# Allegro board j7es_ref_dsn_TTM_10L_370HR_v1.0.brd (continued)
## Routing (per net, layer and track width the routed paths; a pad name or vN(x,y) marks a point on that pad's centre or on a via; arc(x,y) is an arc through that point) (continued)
SOC_SERDES2_REFCLK_P: length 43.3
  TOP w0.122: U9.AD12 101.05,78.95 v1(101.45,79.35)
  L4-SIGNAL w0.099: TPX426.1 99.16,120.77 arc(99.26,120.75) 99.33,120.7 99.34,120.69 arc(99.38,120.64) 99.39,120.58 99.39,120.57 arc(99.39,120.55) 99.39,120.53 99.39,119.58 arc(99.31,119.18) 99.08,118.84 arc(98.92,118.59) 98.86,118.29 98.86,102.57 arc(98.96,102.06) 99.24,101.63 99.78,101.1 arc(100.26,100.38) 100.43,99.52 100.43,89.51 arc(100.56,88.87) 100.92,88.32 100.94,88.3 arc(101.13,88.02) 101.19,87.7 101.19,83.94 101.07,83.48 101.07,80.09 arc(101.07,80.04) 101.07,79.99 arc(101.15,79.72) 101.31,79.49 v1(101.45,79.35)
SOC_SERDES4_REFCLK_N: length 50.2
  TOP w0.119: U9.E7 v1(105.45,63.35)
  L9-SIGNAL w0.076: TPX396.1 132.94,27.07 132.94,30.91 131.02,32.83 128.99,32.83 114.51,47.31 114.51,47.31 106.25,55.56 106.25,59.55 106.61,59.91 106.61,61.09 106.4,61.3 106.19,61.3 105.81,61.69 105.81,62.69 105.45,63.05 v1(105.45,63.35)
SOC_SERDES4_REFCLK_P: length 50.4
  TOP w0.119: U9.E8 v1(104.65,63.35)
  L9-SIGNAL w0.076: v1(104.65,63.35) 105.1,62.9 105.1,62.4 105.31,62.19 105.31,62.1 105.1,61.89 105.1,61.6 105.31,61.39 105.51,61.39 105.81,61.09 105.81,59.79 106.04,59.55 106.04,55.48 114.42,47.1 114.43,47.1 128.9,32.63 130.94,32.63 132.74,30.83 132.74,27.07 TPX397.1
SOC_TCK: length 31.8
  TOP w0.229: v1(87.05,63.35) 87.45,63.75 U9.E29 ; J1011.3 v1(53.85,55.6)
  L4-SIGNAL w0.097: v1(87.05,63.35) 60.43,63.35 v1(58.8,61.71)
  BOTTOM w0.229: 53.09,55.62 53.1,55.6 v1(53.85,55.6)
SOC_TDI: length 77.9
  TOP w0.191: U9.V1 110.25,74.54 v1(110.25,74.55)
  TOP w0.229: U131.4 v1(58.15,50.27)
  BOTTOM w0.127: v1(58.15,50.27) 59.18,51.3 59.18,52.82 60.58,54.22 72.26,54.22 76.96,58.92 96.14,58.92 96.52,58.54 112.01,58.54 112.78,59.3 112.78,73.14 111.37,74.55 v1(110.25,74.55)
SOC_TDO: length 75.3
  TOP w0.191: v1(108.65,74.55) 108.65,74.54 U9.V3
  TOP w0.229: U130.2 v1(58.17,56)
  BOTTOM w0.127: v1(58.17,56) 59.18,54.98 71.95,54.98 76.65,59.68 96.45,59.68 96.84,59.3 111.7,59.3 112.01,59.61 112.01,72.49 111.4,73.11 109.54,73.11 109.06,73.59 109.06,74.14 v1(108.65,74.55)
SOC_TMS: length 76.5
  TOP w0.191: v1(109.45,74.55) 109.05,74.15 U9.V2
  TOP w0.229: U129.4 v1(58.15,52.81)
  BOTTOM w0.127: v1(58.15,52.81) 59.94,54.6 72.11,54.6 76.8,59.3 96.3,59.3 96.68,58.92 111.86,58.92 112.39,59.46 112.39,72.89 111.12,74.16 109.85,74.16 v1(109.45,74.55)
  BOTTOM w0.229: R1219.2 v1(44.96,55.36)
SOC_TRST#: length 50.2
  TOP w0.229: U9.F24 91.05,64.15 v1(91.05,64.15)
  L7-SIGNAL w0.097: v1(60.2,57.27) 62.36,55.11 80.04,55.11 83.59,58.66 89.15,58.66 89.88,59.39 89.88,61.9 90.1,62.11 90.4,62.11 90.65,62.36 90.65,63.75 v1(91.05,64.15)
  BOTTOM w0.229: RJ1025.2 50.55,57.9 53.95,57.9 54.14,57.7 54.92,57.7 55.12,57.9 59.56,57.9 v1(60.2,57.27)
SOC_WKUP_I2C0_SCL: length 216.1
  TOP w0.229: v1(90.25,66.55) 90.65,66.95 U9.J25 ; U29.31 71.79,108.67 v1(71.63,108.83) ; R105.2 v1(71.12,57.27) ; U27.31 v1(129.07,92.32)
  L4-SIGNAL w0.097: v1(71.63,108.83) 71,108.2 71,105.53 70.74,105.27 69.22,105.27 68.2,104.26 40.26,104.26 36.2,100.19 36.2,60.06 39.62,56.63 44.49,56.63 44.83,56.98 45.15,56.98 45.96,56.16 54.02,56.16 54.49,56.63 69.34,56.63 69.98,57.27 v1(71.12,57.27)
  L5-PWR/GND w0.097: 127.54,125.34 75.44,125.34 70.48,120.39 70.48,109.97 v1(71.63,108.83)
  L7-SIGNAL w0.097: v1(71.12,57.27) 79.5,57.27 86.75,64.51 89.54,64.51 89.82,64.79 89.82,65.83 90.25,66.27 v1(90.25,66.55)
SOC_WKUP_I2C0_SDA: length 212.3
  TOP w0.229: v1(91.05,65.75) 91.05,65.75 U9.H24 ; U29.30 71.93,109.17 v1(71.63,109.46) ; U27.30 v1(128.57,92.67) ; v1(70.97,56.05) R121.2 70.41,56.05
  L2-SIGNAL w0.097: v1(91.05,65.75) 90.68,65.38 90.16,65.38 89.81,65.03 89.81,64.79 89.6,64.58 88.56,64.58 88.21,64.23 88.21,63.99 88,63.78 86.01,63.78 78.28,56.05 v1(70.97,56.05)
  L4-SIGNAL w0.097: v1(71.63,109.46) 70.77,108.61 70.77,105.69 70.61,105.53 69.09,105.53 68.27,104.71 40.07,104.71 35.94,100.57 35.94,59.81 39.7,56.05 45.76,56.05 46.59,55.22 48.27,55.22 48.99,55.94 52.97,55.94 53.69,55.22 54,55.22 55.16,56.38 55.56,56.38 55.89,56.05 57.68,56.05 58.01,56.38 58.32,56.38 59.05,55.64 70.56,55.64 v1(70.97,56.05)
  L5-PWR/GND w0.097: 122.68,124.83 75.95,124.83 70.87,119.75 70.87,110.23 v1(71.63,109.46)
SPI3_CS0: length 45.6
  TOP w0.191: U9.AA24 91.45,76.55 v1(91.05,76.95)
  L4-SIGNAL w0.097: v1(91.05,76.95) 90.64,76.54 86.64,76.54 86.03,77.16 69.27,77.16 67.16,79.26 47.9,79.26 TPX34.1
SYS_IRQZ: length 21.9
  TOP w0.229: v1(87.85,64.95) 88.25,65.35 U9.G28
  L4-SIGNAL w0.097: TPX237.1 67.72,64.35 78.58,64.35 79.02,64.78 83.16,64.78 83.43,64.51 87.41,64.51 v1(87.85,64.95)
SYS_MCU_PWRDN: length 36.9
  TOP w0.229: v1(91.05,63.35) 91.45,63.75 U9.E24
  L5-PWR/GND w0.097: TPX211.1 67.06,46.47 68.45,47.87 68.45,48.76 68.83,49.14 76.45,49.14 83.95,56.63 89.03,56.63 91.41,59.01 91.41,62.99 v1(91.05,63.35)
TIMER_IO0: length 49.5
  TOP w0.191: U9.V6 105.85,74.15 v1(106.25,74.55)
  L7-SIGNAL w0.097: TPX315.1 142.43,71.24 136.46,77.21 120.02,77.21 118.49,75.68 114.94,75.68 112.46,73.21 107.87,73.21 107.42,73.67 107.42,73.9 107.2,74.11 106.69,74.11 v1(106.25,74.55)
TRD1_N: length 16.7
  TOP w0.112: C2029.1 R2025.1 25.5,41.65 JZ2000.2
TRD1_P: length 16.7
  TOP w0.112: JZ2000.1 25.45,43.3 C2030.1
TRSTPD: length 5.8
  TOP w0.229: J1011.8 v1(44.99,56.6)
  BOTTOM w0.229: RJ1025.1 47.71,56.63 47.68,56.6 v1(44.99,56.6) 44.08,56.62 R1221.1
UART0_CTS#: length 42.6
  TOP w0.191: U9.Y3 108.65,76.14 v1(108.65,76.15)
  L7-SIGNAL w0.097: v1(108.65,76.15) 109.05,76.54 112.98,76.54 113.89,77.46 117.98,77.46 120.02,79.49 137.8,79.49 141.86,75.43 146.18,75.43 TPX313.1
UART0_RTS#: length 54.6
  TOP w0.191: U9.AA2 109.45,76.94 v1(109.45,76.95)
  L9-SIGNAL w0.097: TPX274.1 158.23,76.71 156.86,76.71 156.04,75.89 142.03,75.89 136.65,81.27 131.44,81.27 131.06,81.65 123.23,81.65 122.22,80.63 116.33,80.63 113.03,77.33 109.84,77.33 v1(109.45,76.95)
UART0_RXD: length 40.7
  TOP w0.191: v1(109.45,77.75) 109.45,77.74 U9.AB2
  L7-SIGNAL w0.097: TPX337.1 146.8,76.71 144.49,76.71 144.48,76.7 142.11,76.7 138.9,79.91 119.55,79.91 117.73,78.09 110.43,78.09 110.41,78.12 110.1,78.12 110.08,78.09 109.8,78.09 v1(109.45,77.75)
UART0_TXD: length 46.6
  TOP w0.191: U9.AB3 108.65,77.74 v1(108.65,77.75)
  L5-PWR/GND w0.097: TPX226.1 150.11,77.21 142.49,77.21 138.27,81.43 121.96,81.43 120.19,79.67 112.6,79.67 112.1,79.17 111.44,79.17 110.38,78.11 109.02,78.11 v1(108.65,77.75)
UART1_RXD: length 41
  TOP w0.191: v1(107.85,76.95) 107.45,76.55 U9.AA4
  L5-PWR/GND w0.097: TPX249.1 142.11,76.32 137.42,81.01 122.3,81.01 120.4,79.12 117.36,79.12 115.95,77.71 111,77.71 110.63,77.34 108.25,77.34 v1(107.85,76.95)
UART1_TXD: length 50.1
  TOP w0.191: v1(107.85,77.75) 107.85,77.74 U9.AB4
  L7-SIGNAL w0.097: v1(107.85,77.75) 108.25,78.15 108.79,78.15 109.08,78.44 109.08,78.76 109.3,78.98 109.61,78.98 109.82,79.2 109.82,79.46 110.11,79.75 110.74,79.75 112.31,81.31 138.64,81.31 142.37,77.59 152.27,77.59 TPX312.1
UART2_RXD: length 44
  TOP w0.191: v1(110.25,76.15) 110.25,76.14 U9.Y1
  L5-PWR/GND w0.097: v1(110.25,76.15) 110.96,76.15 111.8,77 116.42,77 117.91,78.49 120.79,78.49 121.88,79.58 136.95,79.58 142.62,73.9 149.22,73.9 TPX298.1
UART2_TXD: length 42.9
  TOP w0.191: v1(107.05,76.15) 106.65,75.75 U9.Y5
  L7-SIGNAL w0.097: TPX248.1 145.53,74.8 144.49,74.8 144.48,74.79 141.99,74.79 138.3,78.48 130.69,78.48 130.06,79.11 120.01,79.11 118.03,77.13 114.12,77.13 112.78,75.78 107.42,75.78 v1(107.05,76.15)
UB981_CLKIN: length 6.9
  BOTTOM w0.229: R3104.2 100.5,23.45 100.46,23.48 R3102.2 ; R3104.2 R3103.2 102.69,23.45 102.76,23.52 U3019.41 ; R3104.2 100.97,24.56 TP3014.1
UB981_CLKIN_25MHZ: length 1.4
  BOTTOM w0.229: R3104.1 U3020.3
UB981_DOUT0_N: length 1.8
  BOTTOM w0.16: FL3030.4 109.12,12.03 108.89,12.26 108.89,12.75 109.38,13.24 C3121.2
UB981_DOUT0_P: length 1.9
  BOTTOM w0.16: C3119.2 107.99,13.25 108.58,12.65 108.58,12.31 108.31,12.03 FL3030.1
UB981_GPIO0: length 0.9
  BOTTOM w0.229: v1(113.92,20.6) 113.84,20.52 U3019.14
UB981_GPIO1: length 2.5
  BOTTOM w0.229: v1(115,21.05) 114.46,20.51 114.46,20.25 114.23,20.02 U3019.15
UB981_GPIO2: length 1.1
  BOTTOM w0.229: v1(103.12,21.74) 103.4,22.02 U3019.38
UB981_GPIO3: length 1.1
  BOTTOM w0.229: v1(103.12,22.76) 103.37,22.52 U3019.39
UB981_IDX: length 3.3
  BOTTOM w0.229: R3113.2 111.51,16.77 ; 111.51,16.77 111.51,17.42 111.34,17.6 U3019.19 ; 111.51,16.77 112.65,16.77 R3112.1
UB981_MODE_SEL0: length 3.4
  TOP w0.229: R3067.1 112.65,16.77 111.51,16.77 ; 111.51,16.77 111.51,17.45 v1(111.87,17.82) ; 111.51,16.77 R3066.2
  BOTTOM w0.229: v1(111.87,17.82) 111.87,17.88 111.83,17.92 U3019.18
UB981_MODE_SEL1: length 2.9
  TOP w0.229: R3065.2 v1(103.89,17.93)
  BOTTOM w0.229: R3065.2 v1(103.89,17.93) 104.14,18.19 104.52,18.19 104.83,18.5 U3019.32
UB981_PDB: length 2.4
  BOTTOM w0.229: 105.03,17.28 105.09,17.28 v1(105.56,17.75) ; 105.03,17.28 R3110.1 ; 105.03,17.28 105.03,17.81 105.34,18.11 U3019.31
UB981_REM_INTB: length 1.9
  BOTTOM w0.229: R3105.1 114.32,21.95 113.75,22.52 U3019.10
UFS0_REF_CLK: length 0.7
  TOP w0.229: R168.1 TPX390.1
UFS0_REF_CLK_R: length 22.5
  TOP w0.191: U9.AE6 105.85,79.75 v1(106.25,80.15)
  TOP w0.229: R168.2 115.85,95.2 v1(115.82,95.23)
  L5-PWR/GND w0.097: v1(115.82,95.23) 115.82,94.85 115.8,94.82 115.8,92.04 114.81,91.05 113.03,91.05 112.11,90.13 110.58,90.13 109.86,89.4 109.86,88.38 105.89,84.42 105.89,80.79 106.25,80.43 v1(106.25,80.15)
UFS0_RST#: length 37
  TOP w0.191: v1(106.25,79.35) 105.85,78.95 U9.AD6
  L5-PWR/GND w0.097: TPX391.1 118.74,108.57 117.73,107.56 117.73,93.21 115.17,90.65 113.14,90.65 111.25,88.76 110.74,88.76 107.22,85.24 107.22,84.15 106.61,83.54 106.61,79.71 v1(106.25,79.35)
UFS0_RX0_N: length 29.8
  TOP w0.122: U9.AH3 108.25,82.15 v1(108.65,82.55)
  L9-SIGNAL w0.099: v1(108.65,82.55) 108.89,82.78 arc(109.02,82.98) 109.07,83.22 109.07,83.49 arc(109.11,83.69) 109.22,83.86 110.83,85.47 arc(111.29,86.16) 111.45,86.98 111.46,86.98 111.46,89.49 arc(111.52,89.81) 111.7,90.08 arc(111.84,90.29) 111.89,90.54 111.89,90.54 111.89,101.87 arc(112.13,103.11) 112.84,104.17 113.63,104.96 arc(114.23,105.36) 114.92,105.5 115.01,105.5 115.04,105.5 arc(115.63,105.62) 116.14,105.96 arc(116.43,106.4) 116.54,106.92 116.54,107.32 arc(116.48,107.59) 116.33,107.81 TPX386.1
UFS0_RX0_P: length 29.9
  TOP w0.122: v1(109.45,83.35) 109.05,82.95 U9.AJ2
  L9-SIGNAL w0.099: v1(109.45,83.35) 109.45,83.49 arc(109.48,83.62) 109.55,83.72 109.72,83.89 arc(109.83,83.94) 109.93,83.89 110.02,83.81 arc(110.23,83.81) 110.23,84.02 110.15,84.11 arc(110.15,84.32) 110.36,84.32 110.37,84.31 arc(110.59,84.31) 110.59,84.52 110.58,84.54 arc(110.53,84.64) 110.58,84.75 111.06,85.24 arc(111.6,86.04) 111.79,86.98 111.79,89.49 arc(111.82,89.69) 111.93,89.85 arc(112.14,90.17) 112.22,90.54 112.22,101.87 arc(112.44,102.99) 113.07,103.94 113.87,104.73 arc(114.35,105.06) 114.93,105.17 114.98,105.17 115.04,105.17 arc(115.76,105.32) 116.37,105.73 arc(116.74,106.28) 116.87,106.92 116.87,107.35 arc(116.91,107.57) 117.03,107.75 TPX387.1
UFS0_RX1_N: length 29.8
  TOP w0.122: U9.AH4 107.45,82.15 v1(107.85,82.55)
  L9-SIGNAL w0.099: TPX388.1 114.43,109.08 arc(114.58,108.86) 114.63,108.59 114.63,108.09 114.63,108.09 arc(114.53,107.59) 114.24,107.16 111.6,104.52 arc(111.06,103.71) 110.87,102.75 110.87,91.65 arc(110.79,91.24) 110.55,90.88 110.21,90.54 arc(109.8,89.92) 109.65,89.2 109.65,88.57 109.65,88.57 arc(109.53,87.95) 109.18,87.43 108.81,87.06 arc(108.4,86.44) 108.25,85.72 108.25,83.28 arc(108.2,82.98) 108.03,82.72 v1(107.85,82.55)
UFS0_RX1_P: length 29.8
  TOP w0.122: U9.AJ3 108.25,82.95 v1(108.65,83.35)
  L9-SIGNAL w0.099: v1(108.65,83.35) 108.58,83.42 108.58,84.21 arc(108.6,84.26) 108.65,84.28 108.98,84.28 arc(109.09,84.33) 109.14,84.44 arc(109.09,84.55) 108.98,84.6 108.66,84.6 arc(108.61,84.62) 108.58,84.67 108.58,85.72 arc(108.7,86.32) 109.04,86.82 109.41,87.19 arc(109.83,87.82) 109.98,88.57 109.98,89.2 arc(110.1,89.8) 110.44,90.3 110.79,90.65 arc(111.09,91.11) 111.2,91.65 111.2,102.75 arc(111.37,103.58) 111.83,104.28 114.48,106.92 arc(114.83,107.46) 114.96,108.09 114.96,108.5 arc(115.03,108.83) 115.21,109.1 TPX389.1
UFS0_TX0_N: length 36.5
  TOP w0.122: v1(106.25,81.75) 105.85,81.35 U9.AG6
  L7-SIGNAL w0.099: TPX385.1 108.1,115.33 arc(107.99,115.16) 107.95,114.96 107.95,106.57 arc(107.81,105.86) 107.41,105.27 106.02,103.87 arc(105.72,103.43) 105.61,102.9 105.61,83.78 arc(105.62,83.74) 105.64,83.71 105.72,83.63 arc(105.79,83.52) 105.82,83.39 105.82,81.62 arc(105.83,81.57) 105.84,81.52 arc(105.91,81.44) 106.02,81.41 arc(106.18,81.48) 106.25,81.64 v1(106.25,81.75)
UFS0_TX0_P: length 36.5
  TOP w0.122: U9.AF7 105.05,80.55 v1(105.45,80.95)
  L7-SIGNAL w0.099: TPX384.1 107.56,115.32 arc(107.66,115.16) 107.7,114.98 107.7,106.57 arc(107.57,105.96) 107.23,105.45 105.84,104.05 arc(105.48,103.52) 105.36,102.9 105.36,83.91 arc(105.33,83.79) 105.27,83.68 105.18,83.6 arc(105.11,83.49) 105.09,83.37 105.09,81.63 arc(105.14,81.34) 105.31,81.09 v1(105.45,80.95)
UFS0_TX1_N: length 37.9
  TOP w0.191: v1(107.05,81.75) 106.65,81.35 U9.AG5
  L7-SIGNAL w0.099: TPX383.1 110.01,116.6 arc(109.89,116.43) 109.86,116.23 109.86,92.16 arc(109.75,91.6) 109.43,91.13 108.57,90.28 arc(108.34,89.92) 108.26,89.51 108.26,87.07 arc(108.18,86.71) 107.98,86.4 107.38,85.8 107.38,85.81 arc(107.24,85.59) 107.19,85.33 107.19,84.78 arc(107.23,84.68) 107.34,84.63 107.57,84.63 arc(107.72,84.48) 107.57,84.33 107.34,84.33 arc(107.23,84.28) 107.19,84.18 107.19,83.98 arc(107.22,83.82) 107.31,83.69 107.36,83.64 arc(107.42,83.55) 107.44,83.44 107.44,82.63 arc(107.39,82.36) 107.24,82.13 107.19,82.09 arc(107.09,81.93) v1(107.05,81.75)
UFS0_TX1_P: length 37.9
  TOP w0.191: U9.AF6 105.85,80.55 v1(106.25,80.95)
  L7-SIGNAL w0.099: TPX382.1 109.41,116.64 arc(109.55,116.43) 109.6,116.18 109.6,92.16 arc(109.51,91.7) 109.25,91.31 108.39,90.46 arc(108.1,90.02) 108,89.51 108,87.07 arc(107.95,86.8) 107.8,86.58 107.2,85.98 arc(107,85.69) 106.93,85.33 106.93,84 arc(106.89,83.8) 106.78,83.63 arc(106.7,83.52) 106.68,83.39 106.68,81.69 arc(106.66,81.61) 106.61,81.53 106.41,81.33 arc(106.29,81.16) v1(106.25,80.95)
USB0_CS: length 0.8
  TOP w0.127: R1010.1 v2(175.9,125.34)
USB0_DATA_N: length 105.3
  TOP w0.157: v1(107.05,83.35) 107.05,83.34 U9.AJ5
  TOP w0.16: U1001.4 173.86,130.29 v1(173.74,130.16)
  BOTTOM w0.127: 107.12,84.06 107.05,84 v1(107.05,83.35)
  BOTTOM w0.16: 107.12,84.06 108.46,85.4 108.46,86.35 110.11,88 110.11,89.4 111.38,90.67 111.38,108.45 126.19,123.26 157.53,123.26 158.8,121.99 168.22,121.99 172.21,125.97 172.21,130.55 172.97,131.31 173.74,131.31 173.99,131.05 173.99,130.42 v1(173.74,130.16)
USB0_DATA_P: length 107.3
  TOP w0.157: v1(106.25,82.55) 106.25,82.54 U9.AH6
  TOP w0.16: v1(174.46,130.15) 174.36,130.25 U1001.5
  BOTTOM w0.127: v1(106.25,82.55) 106.65,82.94 106.65,84.02
  BOTTOM w0.16: v1(174.46,130.15) 174.5,130.15 174.5,130.16 174.29,130.37 174.29,131.18 173.86,131.61 172.85,131.61 171.91,130.67 171.91,126.1 168.1,122.29 158.93,122.29 157.66,123.56 126.06,123.56 111.07,108.57 111.07,90.79 109.8,89.52 109.8,88.13 108.15,86.48 108.15,85.53 106.65,84.02
USB0_DRVVBUS: length 62.9
  TOP w0.127: R1011.1 R1007.1 R1008.1
  TOP w0.191: v1(106.25,73.75) 106.25,73.74 U9.U6
  L5-PWR/GND w0.097: v1(161.04,73.52) 142.37,73.52 136.65,79.24 131.35,79.24 131.22,79.36 130.91,79.36 130.78,79.24 122.05,79.24 120.95,78.14 118.03,78.14 116.59,76.7 111.93,76.7 110.94,75.71 108.5,75.71 108.29,75.5 108.29,75.26 107.94,74.91 107.7,74.91 107.5,74.7 107.5,74.46 107.14,74.11 106.61,74.11 v1(106.25,73.75)
USB0_ID: length 89.2
  TOP w0.191: U9.AC6 106.25,78.54 v1(106.25,78.55)
  TOP w0.229: R3122.1 v1(150.37,132.96)
  L5-PWR/GND w0.097: v1(150.37,132.96) 149.94,133.39 138.86,133.39 128.52,123.05 116.84,123.05 112.14,118.35 112.14,93.26 108.33,89.45 108.33,87.37 105.51,84.55 105.51,84.09 105.08,83.66 105.08,80.81 105.31,80.58 105.59,80.58 105.89,80.28 105.89,78.91 v1(106.25,78.55)
USB0_IMON: length 4.7
  TOP w0.127: C1017.1 R1005.1 TP1002.1 171.07,130.42 171.68,131.03 U1001.1
USB0_RCALIB: length 6.2
  TOP w0.191: v1(106.25,77.75) 105.85,77.35 U9.AB6
  BOTTOM w0.127: v1(106.25,77.75) 106.65,78.14 110.77,78.14 111.09,78.47 R218.1
USB0_STATUS: length 2.3
  TOP w0.127: U1001.17 171.21,133.2 170.18,134.23 R1001.1
USB0_VBUS_OCN: length 2.1
  TOP w0.127: U1001.18 170.81,132.7 170.43,133.09 R1002.1
USB0_VBUS_SOC: length 76.3
  TOP w0.191: v1(105.45,78.55) 105.05,78.15 U9.AC7
  L7-SIGNAL w0.114: v1(105.45,78.55) 105.88,78.98 105.88,79.51 105.89,79.51 106.08,79.71 106.08,79.72 106.09,79.72 106.1,79.72 106.4,79.72 106.68,80 106.68,80.31 106.9,80.52 107.2,80.52 107.48,80.8 107.48,81.11 107.7,81.32 108,81.32 108.28,81.6 108.28,81.91 108.5,82.12 108.76,82.12 109.07,82.43 109.07,83.78 109.47,84.19 110.13,84.19 111.84,85.9 111.84,88.59 111.84,88.6 111.84,88.93 111.84,88.94 111.84,108.99 124.26,121.4 v1(146.05,121.4)
  BOTTOM w0.229: R170.2 148.09,132.96 R169.2 v1(147.07,132.98)
USB1_CS: length 2.4
  BOTTOM w0.127: R1127.2 R1130.1 C1194.1
USB1_DM: length 2.8
  TOP w0.122: FL1001.1 173.2,135.96 173.47,135.69 173.47,134.5 173.36,134.39 U1001.14
USB1_DP: length 2.8
  TOP w0.122: FL1001.4 174.02,135.96 173.75,135.69 173.75,134.5 173.86,134.39 U1001.13
USB1_DRVVBUS: length 63.2
  TOP w0.127: R1009.1 167.26,123.43 166.24,122.42 165.23,122.42 Q1001.2
  TOP w0.191: v1(107.85,74.55) 107.85,74.54 U9.V4
  L7-SIGNAL w0.097: v1(161.54,73.01) 142.75,73.01 137.8,77.97 130.6,77.97 129.88,78.69 120.35,78.69 118.21,76.54 114.52,76.54 112.14,74.16 108.24,74.16 v1(107.85,74.55)
USB1_HUB_D_N: length 89.3
  TOP w0.157: U9.AH7 105.45,82.54 v1(105.45,82.55)
  TOP w0.16: v1(160.78,125.47) 160.55,125.69 160.55,126.13 160.72,126.3 U1002.12
  BOTTOM w0.127: 105.83,84.26 105.83,84.21 105.84,84.17 105.84,84.17 105.86,84.01 105.86,83.2 105.45,82.79 v1(105.45,82.55)
  BOTTOM w0.16: 105.83,84.26 105.83,84.26 105.83,84.33 105.83,85.16 106.76,86.1 106.76,86.73 107.9,87.87 107.9,89.91 109.93,91.94 109.93,109.46 125.98,125.51 158.81,125.51 159.28,125.97 160.27,125.97 v1(160.78,125.47)
USB1_HUB_D_P: length 87
  TOP w0.157: U9.AJ6 106.25,83.34 v1(106.25,83.35)
  TOP w0.16: U1002.11 160.08,126.3 160.25,126.13 160.25,125.69 v1(160.02,125.47)
  BOTTOM w0.127: 106.13,84.32 106.13,84.3 106.14,84.3 106.17,84.05 106.17,83.43 v1(106.25,83.35)
  BOTTOM w0.16: 106.13,84.32 106.13,84.34 106.13,84.34 106.13,85.04 107.06,85.97 107.06,86.6 108.2,87.75 108.2,89.78 110.24,91.81 110.24,109.34 126.11,125.21 158.94,125.21 159.4,125.67 159.82,125.67 v1(160.02,125.47)
USB1_ID: length 77.4
  TOP w0.191: v1(105.45,79.35) 105.45,79.34 U9.AD7
  TOP w0.229: R3123.1 v1(150.37,134.36)
  L7-SIGNAL w0.114: v1(148.84,121.53) 148.46,121.91 124.14,121.91 111.56,109.33 111.56,86.02 110.03,84.49 109.21,84.49 108.23,83.5 108.23,82.39 107.96,82.12 107.66,82.12 107.47,81.93 107.47,81.55 107.24,81.32 107.21,81.32 107.21,81.32 106.9,81.32 106.68,81.11 106.68,80.76 106.43,80.52 106.42,80.52 106.41,80.52 106.1,80.52 105.88,80.31 105.88,79.99 105.89,79.99 105.89,79.78 v1(105.45,79.35)
USB1_RCALIB: length 0.6
  TOP w0.191: v1(103.85,79.35) 103.45,78.95 U9.AD9
USB1_VBUS_SOC: length 86.8
  TOP w0.191: v1(104.65,79.35) 104.65,79.34 U9.AD8
  TOP w0.229: v1(147.19,134.31) R1.1 R4.2
  L5-PWR/GND w0.097: v1(104.65,79.35) 104.65,79.74 104.6,79.79 104.5,79.79 104.29,80 104.29,83.58 105.33,84.61 105.33,84.87 107.95,87.49 107.95,89.65 110.87,92.57 110.87,117.59 116.71,123.43 128.27,123.43 138.56,133.72 146.61,133.72 v1(147.19,134.31)
USB2_DM: length 3.1
  TOP w0.122: U1002.5 160.72,133.66 160.53,133.85 160.53,135.12 160.81,135.4 FL1000.4
USB2_DP: length 3.1
  TOP w0.122: U1002.6 160.08,133.66 160.25,133.82 160.25,135.14 159.99,135.4 FL1000.1
USBC_DIR: length 50.4
  TOP w0.191: U9.W3 108.25,74.95 v1(108.65,75.35)
  L9-SIGNAL w0.097: v1(108.65,75.35) 109.02,75.72 112.68,75.72 117.09,80.13 122.55,80.13 123.31,80.89 130.81,80.89 131.06,80.63 136.27,80.63 141.52,75.38 152.57,75.38 TPX294.1
USBC_SS_RX1_N: length 99.7
  TOP w0.157: v1(103.05,82.55) 103.05,82.54 U9.AH10
  L9-SIGNAL w0.114: v1(154.42,133.97) 154.56,133.83 arc(154.64,133.72) 154.66,133.59 154.66,133.31 arc(154.69,133.15) 154.78,133.01 154.84,132.95 arc(155.03,132.83) 155.26,132.78 157.45,132.78 arc(157.5,132.77) 157.54,132.74 157.84,132.45 arc(157.93,132.31) 157.96,132.14 157.96,131.26 arc(158.02,130.98) 158.18,130.73 158.31,130.61 arc(158.53,130.28) 158.6,129.9 158.6,128.22 arc(158.53,127.84) 158.31,127.51 155.8,125.01 arc(155.35,124.71) 154.83,124.6 119.94,124.6 arc(118.86,124.39) 117.94,123.78 108.61,114.44 arc(108.03,113.57) 107.82,112.54 107.82,112.04 arc(107.72,111.5) 107.41,111.05 106.41,110.04 arc(106.06,109.52) 105.94,108.91 105.93,108.9 105.93,94.29 105.94,94.27 arc(105.84,93.76) 105.54,93.32 105,92.78 arc(104.53,92.07) 104.37,91.24 104.37,89.84 arc(104.31,89.54) 104.13,89.28 104.05,89.19 103.97,89.12 103.97,89.12 arc(103.9,88.96) 103.87,88.79 103.87,84.33 arc(103.85,84.25) 103.81,84.19 103.69,84.07 arc(103.53,83.84) 103.48,83.55 103.48,83.25 arc(103.43,83) 103.29,82.78 v1(103.05,82.55)
  BOTTOM w0.16: FL3028.4 154.41,134.9 154.42,134.89 v1(154.42,133.97)
USBC_SS_RX1_P: length 99.7
  TOP w0.157: U9.AJ9 103.85,83.34 v1(103.85,83.35)
  L9-SIGNAL w0.114: v1(155.18,133.97) 154.98,133.78 arc(154.93,133.7) 154.92,133.61 154.92,133.35 arc(154.94,133.25) 155,133.16 155,133.15 arc(155.13,133.07) 155.29,133.04 157.45,133.04 arc(157.6,133.01) 157.72,132.92 158.02,132.63 arc(158.16,132.41) 158.22,132.14 158.22,131.26 arc(158.25,131.07) 158.36,130.91 158.49,130.78 arc(158.76,130.38) 158.86,129.9 158.86,128.22 arc(158.76,127.74) 158.49,127.33 155.98,124.83 arc(155.45,124.47) 154.83,124.35 119.94,124.35 arc(118.96,124.15) 118.12,123.6 108.79,114.26 arc(108.26,113.47) 108.08,112.54 108.08,112.04 arc(107.95,111.42) 107.61,110.9 106.58,109.87 arc(106.29,109.43) 106.18,108.91 106.18,94.27 arc(106.06,93.66) 105.71,93.15 105.17,92.61 arc(104.76,91.98) 104.61,91.24 104.61,89.84 arc(104.53,89.44) 104.3,89.11 104.22,89.02 104.22,89.02 arc(104.15,88.91) 104.12,88.79 104.12,88.54 arc(104.17,88.43) 104.27,88.39 104.4,88.39 arc(104.57,88.22) 104.4,88.04 104.29,88.04 arc(104.17,87.99) 104.12,87.87 104.12,86.3 arc(104.16,86.2) 104.26,86.16 arc(104.38,86.11) 104.43,85.99 arc(104.38,85.87) 104.26,85.82 arc(104.16,85.78) 104.12,85.68 104.12,84.28 arc(104.09,84.15) 104.02,84.04 103.94,83.96 arc(103.88,83.87) 103.86,83.77 103.86,83.36 v1(103.85,83.35)
  BOTTOM w0.16: v1(155.18,133.97) 155.18,134.88 155.21,134.91 FL3028.1
USBC_SS_RX2_N: length 118.1
  TOP w0.157: U9.AH9 103.85,82.54 v1(103.85,82.55)
  L9-SIGNAL w0.114: v1(103.85,82.55) 104.09,82.79 arc(104.2,82.95) 104.24,83.15 104.24,83.31 arc(104.28,83.49) 104.39,83.65 104.6,83.81 105.16,84.37 arc(105.31,84.59) 105.36,84.86 105.36,90.72 arc(105.47,91.28) 105.79,91.75 106.48,92.44 arc(106.82,92.94) 106.93,93.53 106.93,108.06 arc(107.06,108.66) 107.4,109.18 108.39,110.16 108.4,110.2 arc(108.67,110.6) 108.77,111.09 108.77,112.02 arc(108.86,112.44) 109.1,112.8 119.19,122.9 arc(119.87,123.35) 120.67,123.51 160.94,123.51 arc(161.63,123.37) 162.22,122.98 162.51,122.69 162.51,122.67 arc(163,122.34) 163.57,122.23 174.73,122.23 arc(175.54,122.39) 176.22,122.85 179.02,125.65 arc(179.26,126.01) 179.35,126.45 179.35,133.56 arc(179.32,133.7) 179.24,133.82 v1(179.09,133.97)
  BOTTOM w0.16: v1(179.09,133.97) 179.09,134.87 FL1002.4
USBC_SS_RX2_P: length 118.1
  TOP w0.157: U9.AJ8 104.65,83.34 v1(104.65,83.35)
  L9-SIGNAL w0.114: v1(104.65,83.35) 104.66,83.36 104.66,83.39 arc(104.68,83.52) 104.76,83.63 105.35,84.22 arc(105.54,84.51) 105.61,84.86 105.61,85.14 arc(105.65,85.22) 105.73,85.25 106.08,85.25 arc(106.3,85.48) 106.08,85.7 105.79,85.7 arc(105.66,85.75) 105.61,85.88 105.61,90.72 arc(105.71,91.18) 105.97,91.57 106.66,92.26 arc(107.05,92.85) 107.19,93.53 107.18,93.55 107.18,108.06 arc(107.28,108.57) 107.57,109.01 arc(107.58,109.02) 107.59,109.03 108.58,110.02 arc(108.91,110.51) 109.03,111.09 109.03,112.01 109.01,112.02 arc(109.08,112.35) 109.27,112.63 119.34,122.71 arc(119.95,123.11) 120.67,123.26 160.94,123.26 arc(161.53,123.14) 162.04,122.8 162.34,122.5 arc(162.91,122.12) 163.57,121.99 174.73,121.99 arc(175.63,122.17) 176.39,122.68 179.19,125.47 arc(179.49,125.92) 179.59,126.45 179.6,126.67 179.6,133.55 179.59,133.56 arc(179.63,133.71) 179.71,133.84 v1(179.85,133.97)
  BOTTOM w0.16: FL1002.1 179.85,134.9 v1(179.85,133.97)
USBC_SS_TX1_N: length 1.4
  BOTTOM w0.16: FL3029.4 156.46,134.89 C219.2
USBC_SS_TX1_P: length 1.4
  BOTTOM w0.16: C218.2 157.23,134.89 FL3029.1
USBC_SS_TX2_N: length 1.6
  BOTTOM w0.16: C217.2 181.33,133.72 181.33,134.38 181.08,134.63 FL1003.4
USBC_SS_TX2_P: length 1.6
  BOTTOM w0.16: FL1003.1 181.89,134.64 181.64,134.38 181.64,133.72 C216.2
VCAP_MCU_VDDS0: length 0.6
  TOP w0.305: U9.K23 92.25,67.75 v1(91.85,67.35)
VCAP_MCU_VDDS1: length 0.6
  TOP w0.305: v1(95.85,66.55) 96.25,66.95 U9.J18
VCAP_MCU_VDDS2: length 0.6
  TOP w0.305: U9.J19 95.45,66.95 v1(95.05,66.55)
VCAP_VDDS0: length 0.6
  TOP w0.305: U9.U7 105.05,73.35 v1(105.45,73.75)
VCAP_VDDS1: length 0.6
  TOP w0.305: v1(93.45,77.75) 93.85,77.35 U9.AB21
VCAP_VDDS2: length 0.6
  TOP w0.305: U9.Y18 96.26,75.75 v1(95.86,76.15)
VCAP_VDDS3: length 0.6
  TOP w0.305: U9.W21 v1(93.45,75.35)
VCAP_VDDS4: length 0.6
  TOP w0.305: U9.AA22 93.05,76.55 v1(92.65,76.95)
VCAP_VDDS5: length 0.6
  TOP w0.305: v1(92.65,71.35) 93.05,71.75 U9.R22
VCAP_VDDS6: length 0.6
  TOP w0.305: v1(92.66,74.55) 93.06,74.15 U9.V22
VDA_DLL_0V8: length 2.1
  TOP w0.305: C512.1 130.68,102.79 130.57,102.68 v1(130.57,102.1) U27.9
  vias: v1(122.44,44.06) v2(114.3,96.26) v2(116.2,100.71) v2(153.29,58.92)
VDA_MCU_1V8: length 6.8
  TOP w0.305: v1(92.65,65.75) 93.04,66.14 U9.H22 93.05,66.15 ; U27.7 v1(131.57,102.1) 131.57,102.1 131.57,102.89 C511.1 ; v1(91.85,68.95) 92.25,69.35 U9.M23 ; v1(92.65,69.75) 93.05,70.15 U9.N22 ; v1(95.85,64.95) 96.25,65.35 U9.G18 ; U9.P22 93.05,70.95 v1(92.65,70.55) ; U9.P21 93.85,70.95 v1(93.45,70.55)
  BOTTOM w0.305: R272.2 v2(134.24,113.4)
  BOTTOM w0.508: 60.78,71.15 60.7,71.24 ; 60.78,71.15 60.83,71.2 60.78,71.15
  vias: v1(61.98,71.11) v1(63.5,71.11) v2(66.67,70.98) v2(68.64,70.98) v2(74.04,33.39) v2(74.93,33.39)
VDA_PLL_1V8: length 8.1
  TOP w0.305: U9.H9 v1(103.85,65.75) ; U9.Y20 v1(94.25,76.15) ; v1(101.45,68.15) U9.L12 ; U9.R11 101.86,71.75 v1(101.46,71.35) ; U29.7 v1(81.15,106.17) 81.16,106.16 81.94,106.16 C543.1 ; U9.M17 97.05,69.35 v1(96.65,68.95) ; v1(96.66,75.35) 97.06,74.95 U9.W17 97.05,74.95 ; U9.P9 103.45,70.95 v1(103.85,70.55) ; v1(98.25,75.35) 98.65,74.95 U9.W15 ; U9.R21 93.85,71.75 v1(93.45,71.35) ; U9.W18 96.26,74.95 v1(95.86,75.35)
  vias: v2(89.41,88) v2(90.93,85.51) v2(92.58,90.41) v2(92.58,88.3)
VDA_USB_3V3: length 38.4
  TOP w0.305: v1(103.05,77.75) 102.65,77.35 U9.AB10 ; U29.11 v1(81.15,108.17) 81.89,108.17 82.09,108.37 C545.1
  TOP w0.381: C34.1 91.2,100.18 91.2,99 91.66,98.54 v1(92.2,98.54)
  TOP w0.508: C35.1 90.93,100.89 91.2,100.62 91.2,100.18
  L4-SIGNAL w0.152: v1(103.05,77.75) 102.66,77.36 102.66,76.8 102.42,76.56 98.89,76.56 98.64,76.8 98.64,77.11 98.4,77.36 98.09,77.36 97.84,77.6 97.84,77.91 97.6,78.16 97.29,78.16 97.04,78.4 97.04,78.71 96.8,78.96 96.49,78.96 96.26,79.19 96.26,79.5 96,79.76 95.69,79.76 95.45,79.99 95.45,84.65
  L4-SIGNAL w0.305: v1(92.2,98.54) 92.71,98.54 92.84,98.41 94.11,98.41 95.45,97.07 95.45,84.65
VIO_3V3: length 13.4
  TOP w0.508: R1033.1 v2(182.25,55.49)
  BOTTOM w0.508: v2(182.25,55.49) 183.26,54.47 183.26,47.49 186.18,44.57
VMON_VEXT: length 27.6
  TOP w0.229: U9.V19 v1(95.05,74.55)
  L9-SIGNAL w0.152: v1(95.05,74.55) 94.63,74.13 94.63,73.94 94.65,73.91 94.65,73.59 94.42,73.36 94.38,73.36 93.92,72.89 86.87,72.89 86.78,72.8 86.4,72.8 86.36,72.76
  L9-SIGNAL w0.305: 86.36,72.76 85.85,72.76 85.34,72.25 79.25,72.25 78.74,71.74 74.8,71.74 71.95,74.6 v1(70.68,74.6)
VMON_VSYS: length 12.3
  TOP w0.305: v1(89.45,68.95) 89.85,69.35 U9.M26 ; v2(82.91,67.15) 82.86,67.1 C132.1 82.22,67.55 81.8,67.97 81.79,67.97 81.77,67.99 R87.1 R84.2
  L7-SIGNAL w0.152: v1(89.45,68.95) 89.04,68.54 86.46,68.54
  L7-SIGNAL w0.305: v2(82.91,67.15) 85.06,67.15 86.46,68.54
VOSNS: length 6.2
  TOP w0.305: U1008.12 176.66,50.53 178.18,49.01 C1061.2 R1039.2
VOUT0_DATA0/PRG1_RGMII2_RD0: length 48.9
  TOP w0.191: v1(92.65,80.15) 93.05,79.75 U9.AE22
  L7-SIGNAL w0.097: v1(92.65,80.15) 92.21,80.58 92.21,84.05 91.16,85.1 85.57,85.1 82.3,88.38 50.67,88.38 TPX150.1
VOUT0_DATA1/PRG1_RGMII2_RD1: length 47.5
  TOP w0.191: U9.AG23 92.25,81.35 v1(91.85,81.75)
  L7-SIGNAL w0.097: TPX126.1 49.65,88.14 63.62,88.14 66.93,84.83 90.17,84.83 91.44,83.56 91.44,82.16 v1(91.85,81.75)
VOUT0_DATA2/PRG1_RGMII2_RD2: length 45.9
  TOP w0.191: U9.AF23 92.25,80.55 v1(91.85,80.95)
  L7-SIGNAL w0.097: TPX177.1 50.92,86.87 61.46,86.87 64.08,84.25 89.21,84.25 89.88,83.58 89.88,83.2 90.16,82.92 90.4,82.92 90.68,82.64 90.68,82.4 90.9,82.18 91.14,82.18 91.48,81.84 91.48,81.32 v1(91.85,80.95)
VOUT0_DATA3/PRG1_RGMII2_RD3: length 50.2
  TOP w0.191: U9.AD23 92.25,78.95 v1(91.85,79.35)
  L7-SIGNAL w0.097: v1(91.85,79.35) 91.42,79.78 90.9,79.78 90.68,80 90.68,81.04 90.4,81.32 90.15,81.32 89.81,81.65 89.81,81.9 89.6,82.11 89.35,82.11 89.01,82.45 89.01,82.7 88.8,82.91 88.55,82.91 88.21,83.25 88.21,83.5 88,83.71 62.32,83.71 60.32,85.71 46.99,85.71 TPX127.1
VOUT0_DATA4/PRG1_RGMII2_RX_CTL: length 43
  TOP w0.191: U9.AH24 91.45,82.15 v1(91.05,82.55)
  L7-SIGNAL w0.097: TPX101.1 51.82,87.24 63.5,87.24 66.17,84.56 89.92,84.56 90.68,83.81 90.68,82.92 v1(91.05,82.55)
VOUT0_DATA5/MCAN6_RX: length 45.8
  TOP w0.191: v1(93.45,81.75) 93.85,81.35 U9.AG21
  L7-SIGNAL w0.097: v1(93.45,81.75) 93.88,82.18 93.88,85.21 91.85,87.24 84.33,87.24 82.55,89.02 TPX175.1
VOUT0_DATA6/PRG1_RGMII2_RXC: length 47.2
  TOP w0.191: v1(91.85,80.15) 92.25,79.75 U9.AE23
  L7-SIGNAL w0.097: TPX151.1 49.17,86.07 60.6,86.07 62.64,84.04 88.65,84.04 89.08,83.6 89.08,83.2 89.3,82.98 89.6,82.98 89.88,82.7 89.88,82.4 90.1,82.18 90.4,82.18 90.68,81.9 90.68,81.6 90.9,81.38 91.17,81.38 91.48,81.07 91.48,80.51 v1(91.85,80.15)
VOUT0_DATA7/MCAN7_TX: length 51
  TOP w0.191: v1(93.45,78.55) 93.85,78.15 U9.AC21
  L9-SIGNAL w0.097: v1(93.45,78.55) 93.01,78.98 93.01,79.57 92.8,79.78 92.5,79.78 92.28,80 92.28,80.23 91.93,80.58 91.7,80.58 91.48,80.8 91.48,81.03 91.48,81.03 91.48,83.64 87.75,87.37 56.9,87.37 54.61,89.65 50.67,89.65 TPX50.1
VOUT0_DATA8/MCAN7_RX: length 46.9
  TOP w0.191: U9.Y23 v1(91.85,76.15)
  L9-SIGNAL w0.097: v1(91.85,76.15) 91.41,76.58 90.9,76.58 90.68,76.8 90.68,77.2 90.5,77.38 90.1,77.38 89.88,77.6 89.88,78 89.7,78.18 86.58,78.18 85.98,77.59 55.88,77.59 55.37,77.08 48.01,77.08 TPX186.1
VOUT0_DATA9/PRG1_UART0_RXD: length 46.5
  TOP w0.191: v1(93.45,80.95) 93.85,80.55 U9.AF21
  L7-SIGNAL w0.097: v1(93.45,80.95) 93.08,81.32 93.08,84.22 91.39,85.91 85.27,85.91 82.56,88.63 52.97,88.63 TPX125.1
VOUT0_DATA10/PRG1_UART0_TXD: length 46.2
  TOP w0.191: v1(91.85,77.75) 92.25,77.35 U9.AB23
  L4-SIGNAL w0.097: TPX58.1 48.01,79.62 67.56,79.62 69.8,77.38 86.12,77.38 86.16,77.34 91.44,77.34 v1(91.85,77.75)
VOUT0_DATA11/PRG1_RGMII2_TD0: length 46
  TOP w0.191: U9.AJ25 90.65,82.95 v1(90.25,83.35)
  L9-SIGNAL w0.097: v1(90.25,83.35) 90.25,83.86 87.5,86.6 56.13,86.6 54.6,88.14 48.38,88.14 TPX26.1
VOUT0_DATA12/PRG1_RGMII2_TD1: length 46.2
  TOP w0.191: v1(90.25,82.55) 90.65,82.15 U9.AH25
  L9-SIGNAL w0.097: TPX73.1 47.9,86.88 54.71,86.88 57.02,84.57 83.06,84.57 83.57,85.08 88.6,85.08 89.82,83.86 89.82,82.98 v1(90.25,82.55)
VOUT0_DATA13/PRG1_RGMII2_TD2: length 48.7
  TOP w0.191: U9.AG25 90.65,81.35 v1(90.25,81.75)
  L9-SIGNAL w0.097: TPX25.1 48.38,89.41 54.22,89.41 56.64,86.98 87.6,86.98 90.62,83.97 90.62,82.12 v1(90.25,81.75)
VOUT0_DATA14/PRG1_RGMII2_TD3: length 42.7
  TOP w0.191: v1(89.45,82.55) 89.85,82.15 U9.AH26
  L9-SIGNAL w0.097: v1(89.45,82.55) 89.08,82.92 88.52,82.92 88.24,83.2 88.24,83.53 87.85,83.92 84.31,83.92 83.95,83.56 70.48,83.56 69.99,83.06 49.65,83.06 TPX3.1
VOUT0_DATA15/PRG1_RGMII2_TX_CTL: length 36.8
  TOP w0.191: U9.AJ27 v1(88.65,83.34)
  L9-SIGNAL w0.097: v1(88.65,83.34) 88.65,83.72 87.93,84.44 84.07,84.44 83.57,83.94 55.12,83.94 TPX27.1
VOUT0_DATA16/PRG1_RGMII1_TD0: length 47.4
  TOP w0.191: U9.AF24 91.45,80.55 v1(91.05,80.95)
  L5-PWR/GND w0.097: v1(91.05,80.95) 91.05,81.13 90.65,81.52 90.65,81.93 90.42,82.16 86.54,82.16 86.03,82.67 57.19,82.67 55.37,80.85 46.78,80.85 TPX178.1
VOUT0_DATA17/PRG1_RGMII1_TD1: length 46.1
  TOP w0.191: v1(91.05,83.35) 91.45,82.95 U9.AJ24
  L5-PWR/GND w0.097: TPX77.1 46.86,83.3 86.3,83.3 86.81,83.81 90.59,83.81 v1(91.05,83.35)
VOUT0_DATA18/PRG1_RGMII1_TD2: length 43
  TOP w0.191: U9.AG24 91.45,81.35 v1(91.05,81.75)
  L5-PWR/GND w0.097: TPX102.1 50.55,82.16 54.74,82.16 55.5,82.92 86.74,82.92 86.77,82.95 90.53,82.95 90.65,82.82 90.65,82.24 91.05,81.84 v1(91.05,81.75)
VOUT0_DATA19/PRG1_RGMII1_TD3: length 41.7
  TOP w0.191: v1(91.05,79.35) 91.45,78.95 U9.AD24
  L5-PWR/GND w0.097: TPX153.1 51.82,79.62 59.68,79.62 60.58,80.52 86.73,80.52 86.75,80.53 90.42,80.53 90.63,80.33 90.63,79.92 91.05,79.5 v1(91.05,79.35)
VOUT0_DATA20/PRG1_RGMII1_TX_CTL: length 43.2
  TOP w0.191: U9.AC24 91.45,78.15 v1(91.05,78.55)
  L5-PWR/GND w0.097: v1(91.05,78.55) 91.05,78.74 90.65,79.14 90.65,79.49 90.4,79.75 78.23,79.75 77.47,78.98 57.66,78.98 57.28,79.36 50.8,79.36 TPX128.1
VOUT0_DATA21/PRG1_RGMII1_TXC: length 40.4
  TOP w0.191: U9.AE24 91.45,79.75 v1(91.05,80.15)
  L5-PWR/GND w0.097: v1(91.05,80.15) 91.05,80.34 90.65,80.74 90.65,81.09 90.4,81.35 86.56,81.35 85.97,80.75 59.8,80.75 59.69,80.63 53.09,80.63 TPX152.1
VOUT0_DATA22/MCAN4_RX: length 28.9
  TOP w0.191: U9.AJ20 94.65,82.95 v1(94.25,83.35)
  L7-SIGNAL w0.097: v1(94.25,83.35) 94.25,85.95 93.22,86.98 93.22,93.97 89.92,97.27 89.92,108.96 TPX147.1
VOUT0_DATA23/SPI6_CS1: length 45.4
  TOP w0.191: v1(94.25,81.75) 94.65,81.35 U9.AG20
  BOTTOM w0.127: v1(94.25,81.75) 93.85,82.14 93.85,85.46 92.07,87.24 57.02,87.24 56.52,87.75 TPX72.1
VOUT0_DE/SPI6_CLK: length 49.7
  TOP w0.191: U9.AC22 93.05,78.15 v1(92.65,78.55)
  L9-SIGNAL w0.097: TPX63.1 48.13,82.03 71.88,82.03 73.03,83.17 83.95,83.17 84.48,83.71 87.21,83.71 87.42,83.5 87.42,83.19 87.69,82.92 88.01,82.92 88.28,82.65 88.28,82.4 88.5,82.18 88.75,82.18 89.08,81.85 89.08,81.6 89.3,81.38 89.55,81.38 89.88,81.05 89.88,80.8 90.1,80.58 90.35,80.58 90.68,80.25 90.68,80 90.9,79.78 91.15,79.78 91.48,79.45 91.48,79.2 91.7,78.98 92.21,78.98 v1(92.65,78.55)
VOUT0_EXTPCLKIN/MCAN6_TX: length 50.5
  TOP w0.191: v1(93.45,82.55) 93.85,82.15 U9.AH21
  BOTTOM w0.127: v1(93.45,82.55) 93.04,82.96 93.04,83.9 91.85,85.09 89.14,85.09 87.87,86.36 55.87,86.36 55.24,86.98 46.99,86.98 TPX173.1
VOUT0_HSYNC/PRG1_RGMII2_TXC: length 39.1
  TOP w0.191: v1(89.45,83.35) 89.85,82.95 U9.AJ26
  L9-SIGNAL w0.097: v1(89.45,83.35) 88.1,84.7 83.69,84.7 83.3,84.3 56.66,84.3 55.12,85.84 53.21,85.84 TPX2.1
VOUT0_PCLK/SPI6_D1: length 44.1
  TOP w0.191: U9.AH22 93.05,82.15 v1(92.65,82.55)
  BOTTOM w0.127: v1(92.65,82.55) 92.21,82.98 92.21,84 91.64,84.57 55.63,84.57 54.48,85.71 52.07,85.71 TPX176.1
VOUT0_VSYNC/SPI6_D0: length 41
  TOP w0.191: U9.AJ22 v1(92.65,83.35)
  BOTTOM w0.127: v1(92.65,83.35) 92.65,83.95 91.77,84.83 78.41,84.83 78.4,84.81 56.53,84.81 54.86,86.48 TPX123.1
VPFE0_DATA6/MCAN5_TX: length 49.3
  TOP w0.191: U9.AJ21 v1(93.45,83.35)
  BOTTOM w0.127: v1(93.45,83.35) 93.45,83.83 92.07,85.21 92.07,86.35 91.44,86.98 55.75,86.98 55.51,87.23 48.02,87.23 TPX97.1
VPFE0_DATA7/MCAN5_RX: length 48.8
  TOP w0.191: v1(93.45,80.15) 93.85,79.75 U9.AE21
  L5-PWR/GND w0.097: v1(93.45,80.15) 93.01,80.59 93.01,83.64 91.69,84.95 80.77,84.95 79.25,86.48 56.13,86.48 55.63,85.97 50.55,85.97 TPX99.1
VPFE0_DATA11/PRG1_MDIO0_MDIO: length 53.2
  TOP w0.191: v1(95.05,79.35) 95.45,78.95 U9.AD19
  L9-SIGNAL w0.097: TPX1.1 52.03,91.01
  L9-SIGNAL w0.102: v1(95.05,79.35) 94.68,79.72 94.68,80.21 94.62,80.28 94.62,80.3 94.4,80.52 94.1,80.52 93.82,80.8 93.82,83.5 93.29,84.03 92.97,84.03 92.97,84.03 92.92,84.03 91.95,85 91.95,85.06 91.95,85.07 91.95,86.35 91.36,86.93 89.79,86.93 88.73,88 88.73,89.8 87.52,91.01 58.13,91.01 58.13,91.01 53,91.01 53,91.01 52.03,91.01
VPFE0_DATA12/PRG1_MDIO0_MDC: length 57.1
  TOP w0.191: U9.AD18 96.25,78.95 v1(95.85,79.35)
  L9-SIGNAL w0.102: v1(95.85,79.35) 95.45,79.74 95.45,80.3 95.2,80.56 94.82,80.56 94.63,80.75 94.63,83.53 94.44,83.71 94.4,83.71 94.4,83.72 94,83.72 93.47,84.24 93.06,84.24 92.84,84.46 92.84,84.47 92.71,84.6 92.71,84.6 92.71,84.6 92.63,84.68 92.63,86.3 91.87,87.06 91.87,89.09 91.08,89.88 89.94,89.88 88.49,91.33 49.81,91.33 TPX49.1
VPP_EFUSE_1V8: length 19.5
  TOP w0.305: U9.F17 97.05,64.55 v1(96.65,64.15) ; U9.AB11 101.85,77.35 v1(102.25,77.75)
  L7-SIGNAL w0.152: v1(102.25,77.75) 101.84,77.33 101.63,77.33 101.62,77.34 101.29,77.34 101.28,77.33 100.83,77.33 100.82,77.34 100.49,77.34 100.48,77.33 100.08,77.33 ; 98.78,66.15 98.12,66.15 98.1,66.14 98.09,66.14 97.86,65.91 97.86,65.61 97.61,65.36 96.53,65.36 96.27,65.1 96.27,64.53 v1(96.65,64.15)
  L7-SIGNAL w0.305: 98.78,66.15 99.06,66.43 99.06,73.01 99.82,73.78 99.82,77.08 100.08,77.33
  vias: v1(114.83,89.3) v1(114.83,88.29) v1(117.37,89.3) v1(117.37,88.29)
VRTC_LEOA_1V8: length 2.1
  TOP w0.305: U27.3 133.57,102.57 v1(133.6,102.61) 133.73,102.73 C510.1
VRTC_LEOB_1V8: length 2.8
  TOP w0.305: C542.1 81.79,104 v1(81.66,104.13) 81.62,104.17 U29.3
  BOTTOM w0.305: R3144.1 v1(81.66,104.13)
VSYS_3V3: length 21.8
  TOP w0.305: U130.5 v2(55.4,55.97) ; C86.1 160.13,111.1 159.35,110.32 U6.4 ; R625.1 v2(57.66,62.85) ; C3145.1 v2(58.29,48.88) ; R1023.2 v2(199.64,96.83) ; R84.1 v2(78.99,66.66) ; U131.5 v2(57.38,52.16) ; U129.5 v2(57.38,53.48) ; U1022.4 v2(21.77,17.21) ; R1022.2 v2(193.17,96.95)
  L9-SIGNAL w0.305: v2(67.94,62.35) 68.31,62.72 68.44,62.72 68.83,63.11 75.96,63.11 78.99,66.14 v2(78.99,66.66)
  BOTTOM w0.305: v2(196.08,99.54) 196.09,99.54 196.09,99.56 196.34,99.81 196.34,100.32
  vias: v1(100.33,24.28) v1(107.14,15.49) v2(25.27,14.21) v2(26.03,14.21) v2(29.59,48.12) v2(160.27,104.76) v2(161.16,105.65) v2(161.16,104.76) v2(162.05,105.65) v2(162.05,104.76) v2(162.94,105.65) v2(162.94,104.76) v2(162.94,102.99) v2(162.94,102.1) v2(162.94,101.21) v2(163.83,105.65) v2(163.83,104.76) v2(163.83,103.88) v2(163.83,102.99) v2(163.83,102.1) v2(163.83,101.21) v2(169.67,107.43) v2(170.18,108.96) v2(170.81,107.43) v2(171.58,107.43) v2(173.86,113.4) v2(174.88,113.4) v2(175.39,139.05) v2(175.9,113.4) v2(176.15,139.05) v2(176.4,8.88) v2(176.4,6.09) v2(176.91,113.4) v2(177.16,110.48) v2(177.16,109.59) v2(177.16,108.7) v2(177.16,107.56) v2(177.16,106.67) v2(177.16,105.53) v2(177.16,104.64) v2(177.16,103.49) v2(177.16,102.61) v2(177.93,113.4) v2(178.31,137.78) v2(178.82,2.15) v2(179.45,8.88) v2(179.45,6.09) v2(181.86,2.15) v2(187.71,111.11) v2(187.81,109.57) v2(187.83,108.83) v2(188.47,110.35) v2(188.59,108.83) v2(188.72,109.59)
VSYS_5V0: length 4.6
  TOP w0.203: v2(193.04,97.91) 193.04,98.41 192.78,98.67 U1007.16
  TOP w0.305: U2007.3 v2(38.73,33.77) ; R1074.2 v2(20.57,11.8)
  BOTTOM w0.305: C2121.1 v2(38.73,33.77)
VSYS_10V5: length 34.2
  TOP w0.305: U1008.24 v2(172.11,59.53) ; L1040.2 146.74,67.6 145.29,66.16 R1106.2
  BOTTOM w0.305: v2(172.11,59.53) 171.12,58.54 165.1,58.54 157.23,66.41 v2(157.23,67.93)
VSYS_16V0: length 30.5
  TOP w0.305: R1110.1 v2(156.84,54.35) ; 191.26,67.68 192.15,66.79 192.15,52.69 187.58,48.12 R1038.2 181.61,48.12 181.48,48.25 R1039.1
  BOTTOM w0.305: C1200.2 v2(180.59,70.47)
  vias: v2(156.97,60.7) v2(158.12,60.7) v2(159.13,60.7) v2(160.15,60.7) v2(181.48,70.47) v2(182.37,70.47) v2(183.26,70.47) v2(184.53,70.47) v2(185.42,70.47) v2(186.31,70.47) v2(187.2,70.47) v2(188.47,70.47) v2(189.36,70.47) v2(190.25,70.47) v2(191.13,70.47) v2(195.83,116.7) v2(196.85,116.7) v2(197.87,116.7) v2(199.14,118.73)
VSYS_SENSE: length 32.7
  TOP w0.254: D2.1 162.49,95.27 v2(162.48,95.27)
  TOP w0.305: D2.1 163.24,96.48 163.4,96.64 R473.2 ; U27.51 v2(134.5,98.15)
  L7-SIGNAL w0.305: v2(134.5,98.15) 135.88,98.15 135.89,98.16 136.53,98.16 137.29,97.4 141.35,97.4 141.73,97.02 160.73,97.02 v2(162.48,95.27)
VUB941_1V1: length 11.6
  TOP w0.381: v1(118.11,31.61) 117.61,31.61 C3054.1 117.51,31.78 v1(117.98,32.25) ; 117.09,24.93 117.09,25.52 v1(117.35,25.77) ; 117.09,24.93 117.7,24.93 117.73,24.95 FL3013.1 119.75,24.95 C3063.1 120.09,23.78 FL3014.1 ; 117.09,24.93 C3061.1 116.39,25.7 v1(116.59,25.9)
  TOP w0.508: FL3012.1 117.45,30.85 C3054.1
VUSB_5V0: length 18.2
  TOP w0.305: v2(161.8,128.77) 161.99,128.58 U1002.14 ; U1002.15 v2(162.62,128.77) ; R1006.1 v2(175.9,127.88)
  TOP w0.508: v2(165.74,127.5) 165.74,128.01 C1012.1 164.72,128.01 v2(164.72,127.5)
  BOTTOM w0.305: v2(161.8,128.77) 161.67,128.64 161.67,127.88 ; 193.55,115.31 v2(192.85,115.31) ; R1125.1 v2(159.64,131.43) ; v2(189.87,123.56) 188.38,122.07 188.38,120.94 188.07,120.64 187.2,120.64 186.44,119.88 R1137.2 ; R1127.1 v2(194.56,121.78)
  vias: v2(172.97,128.51) v2(173.23,127.24) v2(173.23,126.23) v2(192.41,128.26) v2(193.55,128.26) v2(194.56,128.26) v2(195.71,128.26)
WKUP_GPIO0_6: length 49.8
  TOP w0.229: U9.F29 87.45,64.55 v1(87.05,64.15)
  L4-SIGNAL w0.097: TPX18.1 39.24,64.25 41.02,64.25 41.27,64.51 58.68,64.51 59.06,64.12 78.71,64.12 79.05,63.79 86.7,63.79 v1(87.05,64.15)
WKUP_GPIO0_52: length 24.4
  TOP w0.229: U9.E27 88.65,63.35 v1(88.65,63.35)
  L5-PWR/GND w0.097: v1(88.65,63.35) 88.16,62.85 88.05,62.85 88,62.9 87.7,62.9 87.65,62.85 87.25,62.85 87.2,62.9 86.9,62.9 86.85,62.85 78.74,62.85 75.82,59.93 67.06,59.93 TPX253.1
WKUP_LFOSC_XI: length 16.1
  TOP w0.229: U9.N28 88.25,70.15 v1(87.85,69.75) ; R88.1 75.15,67.17 75.35,66.97 76.52,66.97 v1(76.96,67.42)
  L5-PWR/GND w0.097: v1(85.55,69.56) 85.14,69.97 83.95,69.97 81.4,67.42 v1(76.96,67.42)
  L6-PWR/GND w0.097: v1(85.55,69.56) 86.13,69.56 86.32,69.37 87.47,69.37 v1(87.85,69.75)
  BOTTOM w0.229: v1(85.55,69.56) 85.55,68.86 R281.1
WKUP_LFOSC_XO: length 19
  TOP w0.229: v1(89.45,69.75) 89.46,69.75 U9.N26 ; R89.1 72.91,67.55 v1(74.35,67.55)
  L5-PWR/GND w0.097: v1(74.35,67.55) 74.85,68.06 81.66,68.06 83.95,70.35 85.85,70.35 86.9,69.3 89.01,69.3 v1(89.45,69.75)
WKUP_OSC0_XIN: length 13.3
  TOP w0.229: U9.M29 87.45,69.35 v1(87.05,68.95) ; v1(76.96,66.24) 76.95,66.25 Y3.3
  L2-SIGNAL w0.097: v1(76.96,66.24) 80.22,66.24 82.67,68.69 86.79,68.69 v1(87.05,68.95)
WKUP_OSC0_XOUT: length 19.9
  TOP w0.229: v1(88.65,68.95) 88.65,68.95 U9.M27 ; v1(72.39,65.06) 72.4,65.05 Y3.1
  L2-SIGNAL w0.097: v1(88.65,68.95) 88.28,68.58 86.96,68.58 86.87,68.49 86.77,68.49 86.74,68.46 82.83,68.46 80.14,65.78 73.1,65.78 v1(72.39,65.06)
WKUP_UART0_RXD: length 15.2
  TOP w0.229: v1(87.05,66.55) 87.05,66.55 U9.J29
  L5-PWR/GND w0.097: v1(87.05,66.55) 85.27,66.55 82.72,64 76.96,64 75.31,62.35 TPX191.1
WKUP_UART0_TXD: length 24.4
  TOP w0.229: v1(87.85,66.55) 88.25,66.95 U9.J28
  BOTTOM w0.127: v1(87.85,66.55) 87.45,66.15 86.36,66.15 83.31,63.11 78.23,63.11 72.9,57.77 68.33,57.77 TPX165.1
N22073312: length 1.6
  TOP w0.229: U1017.P6 v2(147.66,84.21)
  BOTTOM w0.127: 146.81,84.19 147.64,84.19 v2(147.66,84.21)
N23139394: length 3.3
  BOTTOM w0.229: R170.1 R171.2 148.96,130.8 D1.3
N23154802: length 10.4
  TOP w0.229: R120.1 v1(84.58,56) ; v1(88.65,62.55) 89.05,62.95 U9.D27
  L4-SIGNAL w0.097: v1(88.65,62.55) 89.02,62.18 89.02,59.54 85.47,56 v1(84.58,56)
N24377130: length 49.8
  TOP w0.191: v1(107.85,73.75) 107.85,73.74 U9.U4
  TOP w0.229: R56.1 v1(151.51,71.24)
  L9-SIGNAL w0.097: v1(151.51,71.24) 151.12,71.63 142.36,71.63 137.03,76.95 116.84,76.95 112.65,72.76 108.46,72.76 107.85,73.37 v1(107.85,73.75)
N24594267: length 32.5
  TOP w0.229: v1(69.09,48.63) R137.2 R138.1 ; U9.A23 91.85,60.14 v1(91.85,60.14)
  L9-SIGNAL w0.097: v1(91.85,60.14) 91.85,58.69 90.68,57.52 85.34,57.52 78.27,50.44 78.27,49.56 75.95,47.23 74.17,47.23 72.77,48.63 v1(69.09,48.63)
N27191474: length 24.7
  TOP w0.229: R471.2 v1(158.26,98.01) ; U27.52 v1(136.12,98.65)
  L7-SIGNAL w0.097: v1(136.12,98.65) 136.52,99.05 138.68,99.05 139.45,99.81 143.13,99.81 144.14,98.8 157.48,98.8 v1(158.26,98.01)
N27191486: length 2
  TOP w0.229: U103.4 R471.1
N27191539: length 1.2
  TOP w0.229: R472.2 165.49,96.6 165.45,96.64 R473.1
N28200806: length 3.6
  TOP w0.229: R88.2 76.07,67.64 76.07,69.46 Y2.2 77.68,69.46 C125.1
N28200825: length 4.8
  TOP w0.229: Y2.1 73.48,69.41 C124.1 71.5,69.41 71.2,69.11 71.2,67.68 71.42,67.45 R89.2
N28200987: length 3.2
  TOP w0.229: R67.2 78.7,74.11 C110.1 76.94,74.11 76.7,73.87 Y1.3
N28201033: length 3.2
  TOP w0.229: R77.2 C114.1 72.84,72.43 73.09,72.67 Y1.1
N28832809: length 1.1
  BOTTOM w0.229: C3125.2 R3124.1
N28833063:
  vias: v1(76.83,3.8) v1(76.83,3.16) v1(76.83,2.53)
N28833091: length 1.7
  BOTTOM w0.381: L62.1 L61.2
N28833093: length 1.7
  BOTTOM w0.381: L61.1 87,11.29 L60.2
N28833539: length 8.3
  BOTTOM w0.229: P5.1 L60.1 88.65,14.21
N28846490:
  vias: v1(60.2,3.67) v1(60.2,3.04) v1(60.2,2.4)
N28846519: length 8.3
  BOTTOM w0.229: P6.1 L2019.1 72.01,14.09
N28846523: length 1.7
  BOTTOM w0.381: L2019.2 70.36,11.17 L2020.1
N28846525: length 1.7
  BOTTOM w0.381: L2021.1 L2020.2
N28846680: length 1.1
  BOTTOM w0.229: 65.53,18.91 R3128.1
N28847103:
  vias: v1(43.56,3.55) v1(43.56,2.91) v1(43.56,2.28)
N28847132: length 8.3
  BOTTOM w0.229: P7.1 L2025.1 55.37,13.96
N28847136: length 1.7
  BOTTOM w0.381: L2025.2 53.72,11.04 L2026.1
N28847138: length 1.7
  BOTTOM w0.381: L2027.1 L2026.2
N28847293: length 1.1
  BOTTOM w0.229: 62.48,18.91 R3131.1
N28847749:
  vias: v1(26.92,3.55) v1(26.92,2.91) v1(26.92,2.28)
N28847778: length 8.3
  BOTTOM w0.229: P8.1 L2031.1 38.73,13.96
N28847782: length 1.7
  BOTTOM w0.381: L2031.2 37.08,11.04 L2032.1
N28847784: length 1.7
  BOTTOM w0.381: L2033.1 L2032.2
N28847939: length 1.1
  BOTTOM w0.229: C3144.2 R3134.1
N28898333: length 4
  TOP w0.229: v1(48.13,57.65) 48.08,57.6 J1011.12 ; J1011.1 v1(50.68,55.1)
  BOTTOM w0.229: R3143.2 v1(48.13,57.65)
N28898472: length 3.8
  TOP w0.229: J1011.7 53.75,56.6 53.85,56.5 53.85,56.54 v1(53.86,56.54)
  BOTTOM w0.229: R3135.1 53,56.54 v1(53.86,56.54)
N28898495: length 2.2
  TOP w0.229: J1011.15 v1(53.78,58.6)
  BOTTOM w0.229: 53.09,58.54 53.15,58.6 v1(53.78,58.6)
N28916086: length 14.1
  TOP w0.127: Q13.D 57.45,58.63 57.4,58.57 57.4,58.28 56.64,57.52 56.64,55.56 56.86,55.35 U130.1 57.28,55.24 57.28,54.85 57.15,54.73 55.6,54.73 55.4,54.53 U129.1 55.92,54.11 55.93,54.09 56.01,54.09 56.26,53.84 56.26,51.91 55.92,51.57 U131.1
  TOP w0.229: R625.2 57.66,61.02 57.45,60.82 Q13.D
N28916647: length 16.4
  TOP w0.229: R3136.2 v1(66.67,48.5)
  L9-SIGNAL w0.097: v1(80.75,47.46) 80.15,46.87 78.58,46.87 78.57,46.85 71.75,46.85 71.25,47.36 67.82,47.36 v1(66.67,48.5)
  BOTTOM w0.229: U24.A2 v1(80.75,47.46)
N28916666: length 2.7
  BOTTOM w0.229: R3137.2 79.78,48.97 79.74,48.94 R3138.1 U24.A3 v1(79.75,47.46)
N28964551: length 7.5
  TOP w0.229: U1017.K5 v2(152.66,86.21)
  BOTTOM w0.229: v2(152.66,86.21) 153.42,86.96 153.42,90.03 153.8,90.41 R3141.1 R3142.2
N28998069: length 12.7
  TOP w0.229: U9.F13 100.25,64.54 v1(100.65,64.14)
  L2-SIGNAL w0.097: v1(100.65,64.14) 101.09,63.7 101.09,63.5 101.09,63.5 101.09,63.19 101.09,63.19 101.09,62.7 101.09,62.7 101.09,62.39 101.09,62.39 101.09,61.9 101.09,61.9 101.09,61.59 101.09,61.59 101.09,61.1 101.09,61.1 101.09,60.79 101.09,60.79 101.09,60.3 101.09,60.3 101.09,59.99 101.09,59.99 101.09,53.96 v1(102.36,52.69)
N29139280: length 14.2
  TOP w0.229: U29.40 v1(71.37,104.17)
  L9-SIGNAL w0.097: v1(71.37,104.17) 73.62,104.17 74.04,103.75 82.68,103.75 v1(83.19,103.24)
  BOTTOM w0.229: v1(83.19,103.24) 83.22,103.28 R3144.2
N29153603: length 1.7
  TOP w0.229: R3148.2 TP3020.1
N29154086: length 1.7
  TOP w0.229: R3150.2 TP3021.1
N30074897: length 2.3
  TOP w0.127: U1002.16 163.26,126.04 v2(163.32,125.97)
  BOTTOM w0.127: v2(163.32,125.97) R1133.1
N30074992: length 4.7
  TOP w0.229: U1002.10 v1(159.45,128.58)
  BOTTOM w0.229: TP1003.1 159.26,130.29 159.64,129.91 R1134.2 159.45,129.09 v1(159.45,128.58)
N30075038: length 3.1
  TOP w0.127: Q1001.6 164.58,126.24 v2(164.34,126.48) ; U1002.7 v2(159.45,134.1)
  BOTTOM w0.127: R1125.2 159.64,133.91 v2(159.45,134.1)
N30075044: length 2.4
  TOP w0.127: U1002.8 158.81,133.97 158.69,134.1 158.62,134.1 v2(158.62,134.17)
  BOTTOM w0.127: v2(158.62,134.17) R1126.2
N30411655: length 3.9
  TOP w0.229: U1011.7 TP1018.1 R1164.1
N30703324: length 4.5
  TOP w0.254: 177.29,136.26 176.66,136.26 176.58,136.18 C1005.1 174.36,134.77 U1001.12
N30703458: length 2
  TOP w0.127: R1003.1 170.69,131.94 170.95,132.2 U1001.19
N30703463: length 2.3
  TOP w0.127: U1001.20 171.21,131.7 170.31,130.8 R1004.1
N30746595: length 1.8
  TOP w0.127: RJ1000.2 176.91,133.34 176.77,133.2 U1001.10
N30809211: length 5.1
  TOP w0.203: U1022.3 22.86,17.61 22.61,17.87 21.18,17.87 R1072.2 R1071.1 C1161.2
N30811250: length 6.8
  TOP w0.305: RJ1013.2 R1109.1 155.45,56.63 U1027.5 156.54,58.16 156.84,57.85 R1110.2
N30811520: length 2.2
  TOP w0.305: U1027.3 C1190.1
N30812987: length 2.4
  TOP w0.305: C1189.1 148.21,60.7 U1027.2
N30812990: length 1.5
  TOP w0.305: C1189.2 146.18,62.35 R1091.1
N30812993: length 1.8
  TOP w0.305: R1091.2 149.22,62.6
N30813342: length 6
  TOP w0.305: U1027.4 147.88,58.16 147.45,57.72 R1107.1 C1191.1 R1108.1
N30813649: length 2.4
  TOP w0.305: R1106.1 R1107.2 C1191.2
N30821669: length 2.8
  TOP w0.203: 20.57,13.58 21.34,14.34 21.97,14.34 22.36,14.73 U1022.5
N31193882: length 2.3
  TOP w0.305: R1014.1 165.52,74.37 Q1005.4
N31194203: length 5.8
  TOP w0.305: R1020.1 v2(177.67,69.84) ; Q1003.4 v2(174.97,72.04)
  BOTTOM w0.305: v2(177.67,69.84) 176.28,69.84 174.97,71.15 v2(174.97,72.04)
N31194290: length 3.2
  TOP w0.305: Q1004.4 178.65,71.02 178.94,70.73 R1021.2
N31194295: length 6.3
  TOP w0.305: Q1006.4 v2(180.38,74.37) ; R1015.2 185.08,74.41 v2(185.04,74.37)
  BOTTOM w0.305: v2(180.38,74.37) v2(185.04,74.37)
N31194655: length 2.3
  TOP w0.203: R1034.1 165.81,50.97 D1008.1
N31194670: length 7.3
  TOP w0.203: 170.16,49.93 U1008.2 ; 170.16,49.93 168.75,49.93 168.27,50.41 R1034.2 ; 170.16,49.93 170.69,49.41 C1063.1
N31194787: length 7.3
  TOP w0.305: U1008.26 170.81,59.56 169.67,60.7 C1049.1 167.51,61.58 167.94,62.02 D1007.1
N31194818: length 7.3
  TOP w0.305: D1003.1 174.7,64.89 D1005.1 174.7,62.02 175.01,61.71 C1046.2 175.01,59.93 174.71,59.64 U1008.20
N31196095: length 3.7
  TOP w0.203: U1008.15 178.94,58.03 179.09,58.17 180.07,58.17 C1053.2 180.1,58.14 180.7,58.14 180.85,58.28 R1030.1
